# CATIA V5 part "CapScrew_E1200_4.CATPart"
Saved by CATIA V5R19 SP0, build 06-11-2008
Part number: CapScrew_E1200_4
Nomenclature: E 1200/6x30
Source: Unknown
Description: MEUSBURGER
Bounding box of the stored display mesh (mm): x -4.991 to 4.998, y -5 to 5, z 0 to 36
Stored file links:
  C:\Users\jsmid\Desktop\DP_Smidak_Forma LEGO\CapScrew_E1200_4.CATPart
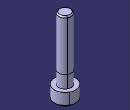
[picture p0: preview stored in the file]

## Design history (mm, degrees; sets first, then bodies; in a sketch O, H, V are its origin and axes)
Body1 (main body)
  Solid1 "PartBody": solid without history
